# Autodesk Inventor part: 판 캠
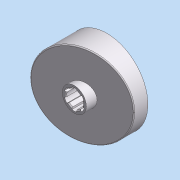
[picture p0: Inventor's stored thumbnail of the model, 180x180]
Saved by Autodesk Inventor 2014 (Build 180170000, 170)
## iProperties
Created: 2012-05
Part Number: 판 캠
Document SubType Name: 모델링
Designer: SeoGD™
Material: 강철
Density: 1 g/cm^3
Appearance: 알루미늄 - 평지
변환 표준: STEP AP214IS
파일 이름: C:\Users\SeoGD\Desktop\?쒗뿕\??stp
전처리기: Build: 253, Release: 2010 SP1 - Date: Wed 07/29/2009
전송 단위: 밀리미터
불확실성: 0.01
Author: SeoGD™
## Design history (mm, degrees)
node "작업 평면4"
sketch "스케치1"
  geometry: C1 r 44.5 at (0, 0); 1 further point
  constraints: 1 centre point, 1 coincident
  dimensions: "d25" = 89 diameter of C1
extrude "돌출1" new body sketch "스케치1" distance "d1" = 40; taper "d2" = 0 deg
sketch "스케치2"
  geometry: L1 (-44.5, 15)-(44.5, 38.847); L2 (-44.5, 0)-(-44.5, 40) reference; L3 (-44.5, 40)-(44.5, 40) reference; L4 (44.5, 0)-(44.5, 40) reference; 1 further point
  constraints: 2 end point, 2 point on line
  dimensions: "d26" = 15 distance of L2.start L1.start; "d27" = 75 deg angle of L1 L2
extrude "돌출2" cut sketch "스케치2" stored distance "d5" = 40; taper "d6" = 0 deg
node "작업 평면1"
sketch "스케치3"
  geometry: C1 r 13 at (0, 0); 1 further point
  constraints: 1 centre point, 1 coincident
  dimensions: "d9" = 26 diameter of C1
extrude "돌출3" join sketch "스케치3" distance "d10" = 38; taper "d11" = 0 deg
hole "구멍1" diameter "d14" = 18; stored, may be unused: countersink angle "d18" = 90 deg, drill point angle "d20" = 118 deg; dims "d12" = 10, "d13" = 10, "d15" = 6, "d16" = 4, "d17" = 2, "d19" = 8
feature "쉘2" dims "d29" = 5
sketch "스케치6"
  geometry: C1 r 17.5 at (0, 0); C2 r 14 at (0, 0) reference; 1 further point
  constraints: 1 centre point, 1 coincident
  dimensions: "d28" = 35 diameter of C1
extrude "돌출4" join sketch "스케치6" stored distance "d30" = 38; taper "d31" = 0 deg
fillet "모깎기1" dims "d32" = 3
chamfer "모따기1" distance "d21" = 1; stored, may be unused: second distance "d22" = 2, angle "d23" = 45 deg
sketch "스케치7"
  geometry: L1 (-12.374, 12.374)-(-27.931, 27.931); A1 r 39.5 centre (0, 0) between (-27.931, 27.931) and (0, 39.5) reference; 2 further points
  constraints: 2 end point, 2 point on circle, 1 point on line, 1 vertical alignment, 2 other
  dimensions: "d33" = 45 deg dimension on point (0, 0) L1.start A1.end
feature "리브1" sketch "스케치7" dims "d34" = 5, "d35" = 1, "d36" = 0
fillet "모깎기2" dims "d37" = 3
sketch "스케치8"
  geometry: L1 (2.5, 10.712)-(2.5, 8.646); L2 (-2.5, 10.712)-(-2.5, 8.646); A1 r 11 centre (0, 0) between (2.5, 10.712) and (-2.5, 10.712); A2 r 9 centre (0, 0) between (2.5, 8.646) and (-2.5, 8.646) reference; 1 further point
  constraints: 4 end point, 4 point on circle, 2 parallel, 1 centre point, 1 coincident, 1 vertical
  dimensions: "d41" = 22 diameter of A1; "d42" = 5 distance between parallel lines of L1 L2
extrude "돌출5" cut sketch "스케치8" stored distance "d43" = 38; taper "d44" = 0 deg
fillet "모깎기3" dims "d48" = 1
node "솔리드1"
node "솔리드 본체"
node "곡면 본체"
pattern_circular "원형 패턴1" dims angle "d39" = 360 deg
pattern_circular "원형 패턴2" dims angle "d46" = 360 deg
node "솔리드2"
